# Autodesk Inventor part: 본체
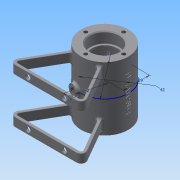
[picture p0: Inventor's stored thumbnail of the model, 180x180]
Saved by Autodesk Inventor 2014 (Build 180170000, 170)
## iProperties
Created: 2016-03
Part Number: 본체
Material: 일반
Document SubType Name: Modeling
Designer: net
Density: 1 g/cm^3
Appearance: 기본값
Author: net
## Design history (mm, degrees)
sketch "스케치1"
  geometry: C1 r 26 at (0, 0); C2 r 21 at (0, 0); 1 further point
  constraints: 2 centre point, 2 coincident
  dimensions: "d0" = 52 diameter of C1; "d3" = 42 diameter of C2
extrude "돌출1" new body sketch "스케치1" stored distance "d1" = 70; taper "d2" = 0 deg
extrude "돌출2" cut sketch "스케치1" stored distance "d4" = 42; taper "d5" = 0 deg
hole "구멍1" diameter "d8" = 28; stored, may be unused: countersink angle "d12" = 90 deg, drill point angle "d14" = 118 deg; dims "d9" = 6, "d10" = 4, "d11" = 2, "d13" = 8, "d15" = 10, "d16" = 10
hole "구멍2" diameter "d19" = 32; stored, may be unused: countersink angle "d23" = 90 deg, drill point angle "d25" = 0 deg; dims "d17" = 10, "d18" = 10, "d20" = 6, "d21" = 4, "d22" = 2, "d24" = 12
node "작업 평면1"
fillet "모깎기1" dims "d26" = 0.3, "d27" = 3
chamfer "모따기1" distance "d28" = 1; stored, may be unused: second distance "d29" = 2, angle "d30" = 45 deg
node "작업 평면2"
sketch "스케치4"
  geometry: L1 (33.934, -65)-(-33.934, -65); L2 (-38.264, -57.5)-(-16.613, -20); L3 (38.264, -57.5)-(16.613, -20); L4 (0, -65)-(0, 0); L5 (-14.183, -21.791)-(-35.666, -59); L6 (-33.934, -62)-(33.934, -62); L7 (35.666, -59)-(14.183, -21.791); C1 r 17 at (0, 0) reference; A1 r 26 centre (0, 0) between (-16.613, -20) and (16.613, -20) reference; A2 r 5 centre (33.934, -60) between (33.934, -65) and (38.264, -57.5); A3 r 5 centre (-33.934, -60) between (-38.264, -57.5) and (-33.934, -65); A4 r 2 centre (-33.934, -60) between (-35.666, -59) and (-33.934, -62); A5 r 2 centre (33.934, -60) between (33.934, -62) and (35.666, -59); 1 further point
  constraints: 14 end point, 12 point on circle, 4 centre point, 4 tangent, 1 coincident, 1 equal radius, 1 horizontal, 1 midpoint, 1 vertical alignment, 2 other
  dimensions: "d35" = 65 distance from line of L1 point (0, 0); "d38" = 45 distance from line of L1 L2.end; "d39" = 30 deg angle of L3 L4; "d40" = 30 deg angle of L2 L4; "d41" = 5 radius of A2; "d42" = 3 distance between parallel lines of L1 L6; "d43" = 3 distance between parallel lines of L2 L5; "d44" = 3 distance between parallel lines of L3 L7
extrude "돌출3" join sketch "스케치4" distance "d45" = 10; taper "d46" = 0 deg
sketch "스케치5"
  geometry: L1 (0, 0)-(0, 29); L2 (0, 0)-(-7.506, -28.012); L3 (0, 0)-(0, -26); L4 (0, 0)-(26, 0); A1 r 26 centre (0, 0) between (0, -26) and (26, 0) reference
  constraints: 8 end point, 2 point on circle, 2 vertical alignment, 1 horizontal alignment
  dimensions: "d47" = 29 distance of L1.start L1.end; "d53" = 29 distance of L1.start L2.end; "d54" = 15 deg angle of L3 L2
node "작업 평면3"
sketch "스케치6"
  geometry: C1 r 5 at (0, 0); 1 further point
  constraints: 1 centre point, 1 coincident
  dimensions: "d48" = 10 diameter of C1
extrude "돌출4" join sketch "스케치6" stored distance "d49" = 10; taper "d50" = 0 deg
node "작업 평면4"
sketch "스케치8"
  geometry: C1 r 6 at (0, 0); 1 further point
  constraints: 1 centre point, 1 coincident
  dimensions: "d55" = 12 diameter of C1
extrude "돌출5" join sketch "스케치8" stored distance "d56" = 10; taper "d57" = 0 deg
node "작업 평면5"
sketch "스케치10"
  geometry: 2 further points
  constraints: 1 coincident, 1 other
feature "엠보싱1" sketch "스케치10" dims "d58" = 0.5, "d59" = 0
sketch "스케치12"
  geometry: L1 (67.868, 10)-(0, 10) reference; L2 (33.934, 5)-(33.934, -45); L3 (67.868, -50)-(0, -50) reference; L4 (13.934, 5)-(13.934, -45); L5 (53.934, 5)-(53.934, -45); 2 further points
  constraints: 6 end point, 2 parallel, 2 vertical alignment, 1 midpoint
  dimensions: "d60" = 5 distance from line of L3 L2.end; "d61" = 5 distance from line of L2.start L1; "d62" = 20 distance between parallel lines of L2 L4; "d63" = 20 distance from line of L5.end L2
hole "구멍3" sketch "스케치12" at (13.934, 5) diameter "d64" = 6; stored, may be unused: countersink angle "d68" = 90 deg, drill point angle "d70" = 0 deg; dims "d65" = 6, "d66" = 4, "d67" = 2, "d69" = 12
fillet "모깎기2" dims "d77" = 0.5
fillet "모깎기3" dims "d78" = 3
sketch "스케치13" dims "d79" = 42
  geometry: L1 (0, 0)-(0, 21); C1 r 26 at (0, 0) reference; C2 r 17 at (0, 0) reference
  constraints: 2 end point, 2 vertical alignment, 2 other
hole "구멍4" sketch "스케치13" at (0, 21) diameter "d80" = 4; stored, may be unused: countersink angle "d84" = 90 deg, drill point angle "d86" = 118 deg; dims "d81" = 6, "d82" = 4, "d83" = 2, "d85" = 10
feature "스레드1" dims "d90" = 8, "d91" = 0
feature "스레드2" dims "d92" = 8, "d93" = 0
feature "스레드3" dims "d94" = 8, "d95" = 0
feature "스레드4" dims "d96" = 8, "d97" = 0
feature "스레드5" dims "d98" = 8, "d99" = 0
feature "스레드6" dims "d100" = 8, "d101" = 0
feature "스레드7" dims "d102" = 8, "d103" = 0
feature "스레드8" dims "d104" = 8, "d105" = 0
fillet "모깎기4" dims "d106" = 2
hole "구멍5" diameter "d109" = 6; stored, may be unused: countersink angle "d113" = 90 deg, drill point angle "d115" = 0 deg; dims "d107" = 10, "d108" = 10, "d110" = 6, "d111" = 4, "d112" = 2, "d114" = 10
hole "구멍6" diameter "d118" = 6; stored, may be unused: countersink angle "d122" = 90 deg, drill point angle "d124" = 0 deg; dims "d116" = 10, "d117" = 10, "d119" = 6, "d120" = 4, "d121" = 2, "d123" = 10
feature "스레드9" dims "d125" = 10, "d126" = 0
feature "스레드10" dims "d127" = 10, "d128" = 0
node "솔리드1"
mirror "대칭1"
mirror "대칭2"
pattern_linear "직사각형 패턴1" dims "d73" = -40
pattern_circular "원형 패턴1" dims angle "d88" = 360 deg
mirror "대칭3"
node "투영된 루프1"
